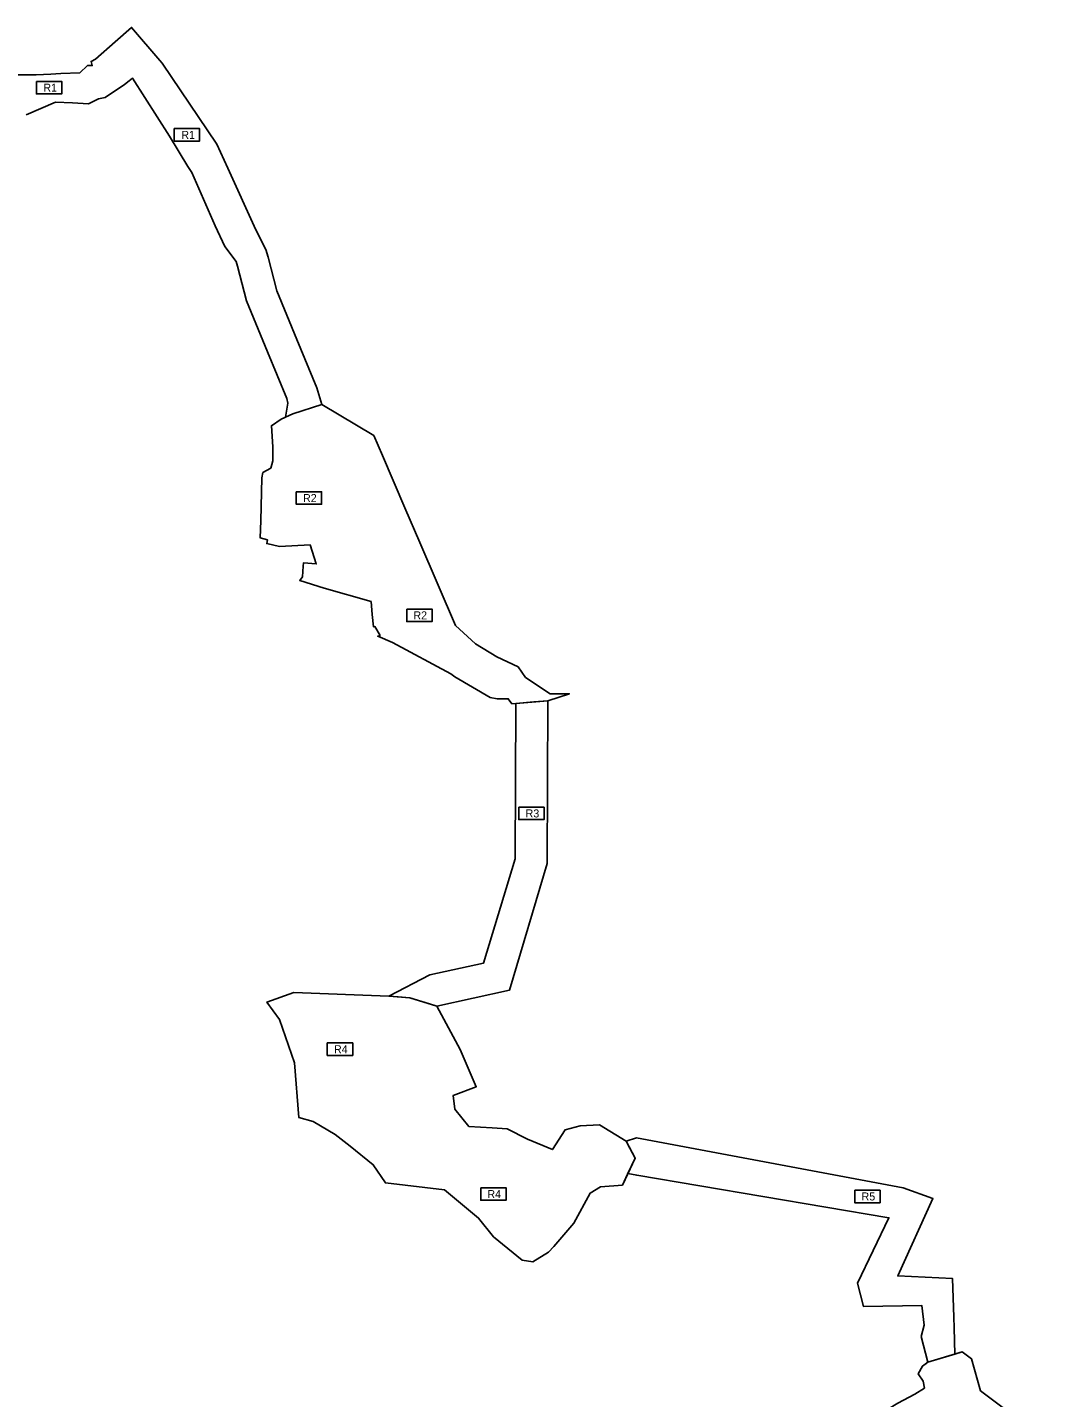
# Model space of a CAD drawing. Extents: x -545342 to -528609, y -1041871 to -1035695.
# Drawn here: x -542574 to -541306, y -1039848 to -1038135 of the extents above; entities that cross this region are included whole.
import ezdxf

# ---------------------------------------------------------------- set-up
doc = ezdxf.new("R2010")
doc.units = 0
for name, color, linetype in [('Vrstva 31', 7, 'Continuous'), ('Vrstva 32', 7, 'Continuous'), ('Vrstva 5', 7, 'Continuous'), ('Vrstva 6', 7, 'Continuous'), ('Vrstva66', 7, 'Continuous')]:
    doc.layers.add(name, color=color, linetype=linetype)

msp = doc.modelspace()

# ---------------------------------------------------------------- linework, layer by layer
at = {"layer": 'Vrstva 31'}
for points in [[(-542591.4, -1038194.5), (-542563.3, -1038194.5), (-542544.9, -1038193.7), (-542532.5, -1038193.1), (-542508.5, -1038192), (-542499.2, -1038183.2), (-542493.2, -1038183.1), (-542494.5, -1038177.9), (-542488.9, -1038174.9), (-542464.4, -1038153.3), (-542443.9, -1038135.4), (-542408.6, -1038176.6), (-542405.7, -1038180.1), (-542337.2, -1038281.4), (-542323.5, -1038311.4), (-542288.5, -1038388.2), (-542284.6, -1038396.1)], [(-542284.6, -1038396.1), (-542281.8, -1038401.7), (-542276.2, -1038412.8), (-542273, -1038422.6), (-542262.3, -1038464.5), (-542237.2, -1038525.6), (-542212.2, -1038585.7), (-542206.1, -1038606.5), (-542242.4, -1038618.3), (-542251.3, -1038622.5), (-542248.6, -1038604.8), (-542250, -1038599), (-542274.2, -1038540.9), (-542300.4, -1038477.1), (-542311.4, -1038433.8), (-542313.3, -1038428.1), (-542327.3, -1038409.3), (-542339.6, -1038383.2), (-542368.8, -1038316.9), (-542373.5, -1038309.2), (-542396.7, -1038271.2), (-542442.8, -1038198.9), (-542447, -1038202.1), (-542452.7, -1038206.8), (-542477.2, -1038223.2), (-542485.5, -1038224.6), (-542497.7, -1038230.9), (-542517.9, -1038229.8), (-542539.1, -1038228.8), (-542575.9, -1038244.5)], [(-542096.2, -1039348.1), (-542122.5, -1039345.9), (-542070.9, -1039319.5), (-542004.1, -1039304.9), (-541964.5, -1039174.3), (-541963.4, -1038980.4), (-541923.4, -1038976.8), (-541924, -1039078.6), (-541924.5, -1039180.3), (-541971.5, -1039338.7), (-542062.4, -1039358.6), (-542096.2, -1039348.1)], [(-541497.1, -1039623), (-541654.8, -1039596.4), (-541812.4, -1039569.9), (-541823.3, -1039567.6), (-541814.2, -1039548.4), (-541825.5, -1039527.1), (-541812.7, -1039523.3), (-541645.9, -1039554.4), (-541479.1, -1039585.5)], [(-541479.1, -1039585.5), (-541441.9, -1039599), (-541486, -1039695.6), (-541417.4, -1039699), (-541415.9, -1039747.1)], [(-541453, -1039757.1), (-541455.7, -1039732.7), (-541528.6, -1039734), (-541536.3, -1039704.6), (-541497.1, -1039623)], [(-541415.9, -1039747.1), (-541415.5, -1039760.6)], [(-541456.5, -1039771.5), (-541453, -1039757.1)], [(-541415.5, -1039760.6), (-541414.6, -1039793.3), (-541448.3, -1039803.6), (-541456.5, -1039771.5)]]:
    msp.add_lwpolyline(points, dxfattribs=at)
at = {"layer": 'Vrstva 32'}
for points in [[(-542144.5, -1038852.9), (-542143, -1038869), (-542141.5, -1038884.4), (-542139.7, -1038884.2), (-542133.2, -1038895.2), (-542136.2, -1038896.3), (-542117.8, -1038904.3), (-542044.9, -1038943.2), (-542039.9, -1038946.9), (-541995.5, -1038972.9), (-541986.7, -1038974.7), (-541973, -1038974.4), (-541968.5, -1038980.9), (-541963.4, -1038980.4), (-541923.4, -1038976.8), (-541896.5, -1038968.1), (-541920.4, -1038968.1), (-541951.5, -1038947.8), (-541960.6, -1038934.5), (-541987.3, -1038921.9), (-542013.8, -1038905.7), (-542038.9, -1038882.8), (-542083.5, -1038779.2), (-542102.2, -1038735.7), (-542130.3, -1038670.2), (-542140.9, -1038645.5), (-542206.1, -1038606.5), (-542242.4, -1038618.3), (-542256.8, -1038625.1), (-542269.1, -1038633.3), (-542267.3, -1038659.4), (-542267.2, -1038677), (-542270, -1038686.2), (-542279.7, -1038691.8), (-542280.9, -1038698.3), (-542282.4, -1038752.2), (-542283, -1038773.4), (-542274.1, -1038775.9), (-542274.9, -1038780.5), (-542258.9, -1038784.2), (-542220.8, -1038782.2), (-542213, -1038805.8), (-542229.1, -1038804.6), (-542229.3, -1038808.6), (-542230.1, -1038821.9), (-542233.7, -1038826.6), (-542203.2, -1038836.2), (-542144.5, -1038852.9)], [(-542012.9, -1039459.2), (-542033.1, -1039412.8), (-542062.4, -1039358.6), (-542096.2, -1039348.1), (-542122.5, -1039345.9), (-542241, -1039341.3), (-542274.7, -1039353.4), (-542259, -1039375.2), (-542240.4, -1039429.6), (-542234.7, -1039497.8), (-542216.8, -1039502.6), (-542189.2, -1039518.9), (-542170.7, -1039533.6)], [(-542052.9, -1039587.9), (-542010.1, -1039623.4), (-541991.3, -1039646.9), (-541955.5, -1039676.1), (-541942.2, -1039678.2), (-541922.5, -1039665.9), (-541916.1, -1039658.8), (-541891.1, -1039629.8), (-541870.4, -1039592.2), (-541857.7, -1039584.2), (-541830.3, -1039582.2), (-541814.2, -1039548.4), (-541825.5, -1039527.1), (-541858.7, -1039507), (-541883.2, -1039508.2), (-541901.9, -1039513.1), (-541917.7, -1039537.9), (-541948.9, -1039524.7), (-541974.5, -1039511.9), (-541993.3, -1039510.6), (-542022.2, -1039508.8), (-542039.7, -1039487.1), (-542041.8, -1039470.2), (-542012.9, -1039459.2)], [(-542170.7, -1039533.6), (-542141.8, -1039556.7), (-542126.6, -1039579.4), (-542052.9, -1039587.9)], [(-541306.1, -1039896.5), (-541382.4, -1039839.1), (-541393.7, -1039799.2), (-541405.3, -1039790.4), (-541448.3, -1039803.6), (-541454.8, -1039808.4), (-541460.3, -1039818.1), (-541454.1, -1039827.2), (-541452.7, -1039835.8), (-541464.4, -1039843.4), (-541485.8, -1039854.9), (-541509, -1039868.7), (-541503, -1039879.2), (-541476.8, -1039885.6), (-541432.3, -1039899.4)]]:
    msp.add_lwpolyline(points, dxfattribs=at)
at = {"layer": 'Vrstva 5'}
for points in [[(-542563, -1038203), (-542531.3, -1038203), (-542531.3, -1038218.5), (-542563, -1038218.5)], [(-542390.6, -1038261.9), (-542358.9, -1038261.9), (-542358.9, -1038277.4), (-542390.6, -1038277.4)], [(-541959.8, -1039110), (-541928.1, -1039110), (-541928.1, -1039125.5), (-541959.8, -1039125.5)], [(-541539.7, -1039588.6), (-541508, -1039588.6), (-541508, -1039604.2), (-541539.7, -1039604.2)]]:
    msp.add_lwpolyline(points, close=True, dxfattribs=at)
at = {"layer": 'Vrstva 6'}
for points in [[(-542238, -1038715.8), (-542206.3, -1038715.8), (-542206.3, -1038731.3), (-542238, -1038731.3)], [(-542099.9, -1038862.4), (-542068.2, -1038862.4), (-542068.2, -1038877.9), (-542099.9, -1038877.9)], [(-542199.2, -1039404.6), (-542167.5, -1039404.6), (-542167.5, -1039420.2), (-542199.2, -1039420.2)], [(-542007.4, -1039585.6), (-541975.7, -1039585.6), (-541975.7, -1039601.1), (-542007.4, -1039601.1)]]:
    msp.add_lwpolyline(points, close=True, dxfattribs=at)
at = {"layer": 'Vrstva66'}
for points in [[(-542251.3, -1038622.5), (-542242.4, -1038618.3), (-542206.1, -1038606.5), (-542212.2, -1038585.7), (-542237.2, -1038525.6), (-542262.3, -1038464.5), (-542273, -1038422.6), (-542276.2, -1038412.8), (-542281.8, -1038401.7), (-542284.6, -1038396.1), (-542288.5, -1038388.2), (-542323.5, -1038311.4), (-542337.2, -1038281.4), (-542405.7, -1038180.1), (-542408.6, -1038176.6), (-542443.9, -1038135.4), (-542464.4, -1038153.3), (-542488.9, -1038174.9), (-542494.5, -1038177.9), (-542493.2, -1038183.1), (-542499.2, -1038183.2), (-542508.5, -1038192), (-542532.5, -1038193.1), (-542544.9, -1038193.7), (-542563.3, -1038194.5), (-542591.4, -1038194.5)], [(-542575.9, -1038244.5), (-542539.1, -1038228.8), (-542517.9, -1038229.8), (-542497.7, -1038230.9), (-542485.5, -1038224.6), (-542477.2, -1038223.2), (-542452.7, -1038206.8), (-542447, -1038202.1), (-542442.8, -1038198.9), (-542396.7, -1038271.2), (-542373.5, -1038309.2), (-542368.8, -1038316.9), (-542339.6, -1038383.2), (-542327.3, -1038409.3), (-542313.3, -1038428.1), (-542311.4, -1038433.8), (-542300.4, -1038477.1), (-542274.2, -1038540.9), (-542250, -1038599), (-542248.6, -1038604.8), (-542251.3, -1038622.5)], [(-541941.1, -1038978.4), (-541923.4, -1038976.8), (-541896.5, -1038968.1), (-541920.4, -1038968.1), (-541951.5, -1038947.8), (-541960.6, -1038934.5), (-541987.3, -1038921.9), (-542013.8, -1038905.7), (-542038.9, -1038882.8), (-542083.5, -1038779.2), (-542102.2, -1038735.7), (-542130.3, -1038670.2), (-542140.9, -1038645.5), (-542206.1, -1038606.5), (-542242.4, -1038618.3), (-542251.3, -1038622.5), (-542256.8, -1038625.1), (-542269.1, -1038633.3), (-542267.3, -1038659.4), (-542267.2, -1038677), (-542270, -1038686.2), (-542279.7, -1038691.8), (-542280.9, -1038698.3), (-542282.4, -1038752.2), (-542283, -1038773.4), (-542274.1, -1038775.9), (-542274.9, -1038780.5), (-542258.9, -1038784.2), (-542220.8, -1038782.2), (-542213, -1038805.8), (-542229.1, -1038804.6), (-542229.3, -1038808.6), (-542230.1, -1038821.9), (-542233.7, -1038826.6), (-542203.2, -1038836.2), (-542144.5, -1038852.9), (-542143, -1038869), (-542141.5, -1038884.4), (-542139.7, -1038884.2), (-542133.2, -1038895.2), (-542136.2, -1038896.3), (-542117.8, -1038904.3), (-542044.9, -1038943.2), (-542039.9, -1038946.9), (-541995.5, -1038972.9), (-541986.7, -1038974.7), (-541973, -1038974.4), (-541968.5, -1038980.9), (-541963.4, -1038980.4), (-541941.1, -1038978.4)], [(-541941.1, -1038978.4), (-541963.4, -1038980.4), (-541964.5, -1039174.3), (-542004.1, -1039304.9), (-542070.9, -1039319.5), (-542122.5, -1039345.9), (-542110.7, -1039346.9), (-542096.2, -1039348.1), (-542071.4, -1039355.8), (-542062.4, -1039358.6), (-541971.5, -1039338.7), (-541924.5, -1039180.3), (-541924, -1039078.6), (-541923.4, -1038976.8), (-541941.1, -1038978.4)], [(-542110.7, -1039346.9), (-542122.5, -1039345.9), (-542241, -1039341.3), (-542274.7, -1039353.4), (-542259, -1039375.2), (-542240.4, -1039429.6), (-542234.7, -1039497.8), (-542216.8, -1039502.6), (-542189.2, -1039518.9), (-542170.7, -1039533.6), (-542141.8, -1039556.7), (-542126.6, -1039579.4), (-542052.9, -1039587.9), (-542010.1, -1039623.4), (-541991.3, -1039646.9), (-541955.5, -1039676.1), (-541942.2, -1039678.2), (-541922.5, -1039665.9), (-541916.1, -1039658.8), (-541891.1, -1039629.8), (-541870.4, -1039592.2), (-541857.7, -1039584.2), (-541830.3, -1039582.2), (-541823.7, -1039568.4), (-541814.2, -1039548.4), (-541820.8, -1039536.1), (-541825.5, -1039527.1), (-541858.7, -1039507), (-541883.2, -1039508.2), (-541901.9, -1039513.1), (-541917.7, -1039537.9), (-541948.9, -1039524.7), (-541974.5, -1039511.9), (-541993.3, -1039510.6), (-542022.2, -1039508.8), (-542039.7, -1039487.1), (-542041.8, -1039470.2), (-542012.9, -1039459.2), (-542033.1, -1039412.8), (-542062.4, -1039358.6), (-542071.4, -1039355.8), (-542096.2, -1039348.1), (-542110.7, -1039346.9)], [(-541820.8, -1039536.1), (-541814.2, -1039548.4), (-541823.3, -1039567.6), (-541812.4, -1039569.9), (-541654.8, -1039596.4), (-541497.1, -1039623), (-541536.3, -1039704.6), (-541528.6, -1039734), (-541455.7, -1039732.7), (-541453, -1039757.1), (-541456.5, -1039771.5), (-541448.3, -1039803.6), (-541414.6, -1039793.3), (-541415.5, -1039760.6), (-541415.9, -1039747.1), (-541417.4, -1039699), (-541486, -1039695.6), (-541441.9, -1039599), (-541479.1, -1039585.5), (-541645.9, -1039554.4), (-541812.7, -1039523.3), (-541825.5, -1039527.1), (-541820.8, -1039536.1)], [(-541450.4, -1039805), (-541454.8, -1039808.4), (-541460.3, -1039818.1), (-541454.1, -1039827.2), (-541452.7, -1039835.8), (-541464.4, -1039843.4), (-541485.8, -1039854.9)], [(-541306.1, -1039896.5), (-541382.4, -1039839.1), (-541393.7, -1039799.2), (-541405.3, -1039790.4), (-541414.6, -1039793.3), (-541448.3, -1039803.6), (-541450.4, -1039805)]]:
    msp.add_lwpolyline(points, dxfattribs=at)

# ---------------------------------------------------------------- texts
at = {"layer": 'Vrstva 5'}
for s, p in [('R1', (-542554.3, -1038215.7)), ('R1', (-542381.8, -1038274.7)), ('R3', (-541951.3, -1039122.7)), ('R5', (-541531.2, -1039601.4))]:
    msp.add_text(s, height=10, dxfattribs=at).set_placement(p)
at = {"layer": 'Vrstva 6'}
for s, p in [('R2', (-542229.6, -1038728.6)), ('R2', (-542091.6, -1038875.2)), ('R4', (-542190.9, -1039417.4)), ('R4', (-541999.1, -1039598.4))]:
    msp.add_text(s, height=10, dxfattribs=at).set_placement(p)

doc.saveas('drawing.dxf')
